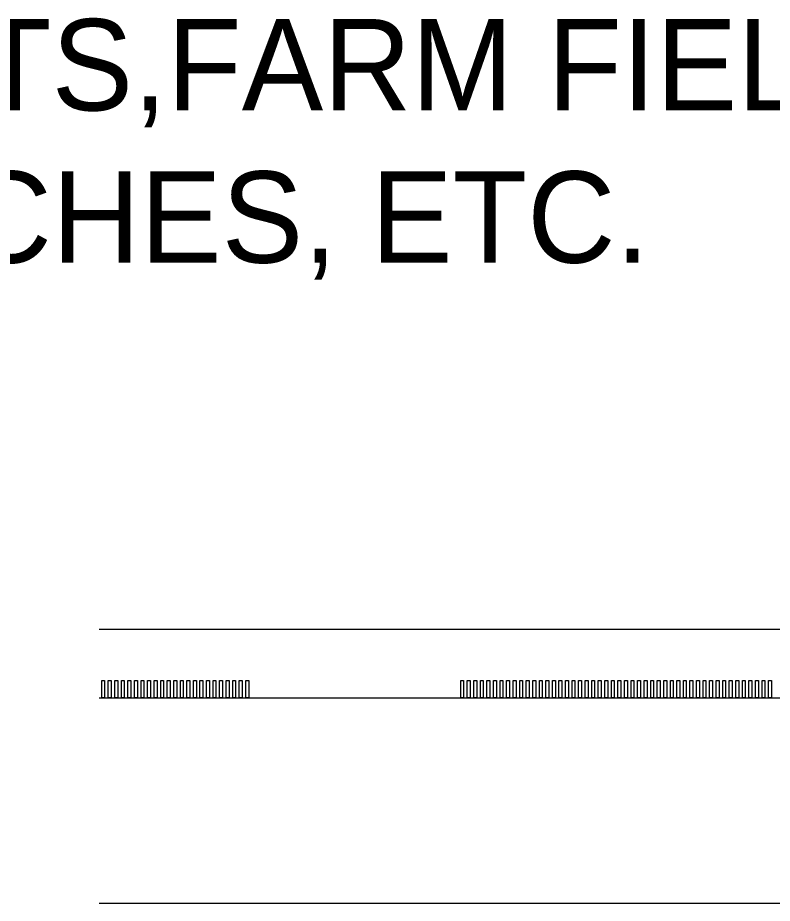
# Model space of a CAD drawing. Extents: x 49991.4 to 50021, y 49987.6 to 50011.4.
# Drawn here: x 50005.072 to 50005.567, y 49992.81 to 49993.391 of the extents above; entities that cross this region are included whole.
import ezdxf

# ---------------------------------------------------------------- set-up
doc = ezdxf.new("R2010")
doc.units = 0
doc.layers.add('Level 1', color=7, linetype='Continuous')
doc.layers.add('Level 2', color=7, linetype='Continuous')

msp = doc.modelspace()

# ---------------------------------------------------------------- linework, layer by layer
at = {"layer": 'Level 1'}
for p, q in [((50005.12506, 49992.9896), (50011.51026, 49992.9896)), ((50005.12506, 49992.9446), (50011.51026, 49992.9446)), ((50005.12506, 49992.8096), (50011.51026, 49992.8096))]:
    msp.add_line(p, q, dxfattribs=at)
for points in [[(50005.12859, 49992.9446), (50005.12669, 49992.9446), (50005.12669, 49992.9558), (50005.12859, 49992.9558)], [(50005.13289, 49992.9446), (50005.13099, 49992.9446), (50005.13099, 49992.9558), (50005.13289, 49992.9558)], [(50005.13719, 49992.9446), (50005.13529, 49992.9446), (50005.13529, 49992.9558), (50005.13719, 49992.9558)], [(50005.14149, 49992.9446), (50005.13959, 49992.9446), (50005.13959, 49992.9558), (50005.14149, 49992.9558)], [(50005.14579, 49992.9446), (50005.14389, 49992.9446), (50005.14389, 49992.9558), (50005.14579, 49992.9558)], [(50005.15009, 49992.9446), (50005.14819, 49992.9446), (50005.14819, 49992.9558), (50005.15009, 49992.9558)], [(50005.15439, 49992.9446), (50005.15249, 49992.9446), (50005.15249, 49992.9558), (50005.15439, 49992.9558)], [(50005.15869, 49992.9446), (50005.15679, 49992.9446), (50005.15679, 49992.9558), (50005.15869, 49992.9558)], [(50005.16299, 49992.9446), (50005.16109, 49992.9446), (50005.16109, 49992.9558), (50005.16299, 49992.9558)], [(50005.16729, 49992.9446), (50005.16539, 49992.9446), (50005.16539, 49992.9558), (50005.16729, 49992.9558)], [(50005.17159, 49992.9446), (50005.16969, 49992.9446), (50005.16969, 49992.9558), (50005.17159, 49992.9558)], [(50005.17589, 49992.9446), (50005.17399, 49992.9446), (50005.17399, 49992.9558), (50005.17589, 49992.9558)], [(50005.18019, 49992.9446), (50005.17829, 49992.9446), (50005.17829, 49992.9558), (50005.18019, 49992.9558)], [(50005.18449, 49992.9446), (50005.18259, 49992.9446), (50005.18259, 49992.9558), (50005.18449, 49992.9558)], [(50005.18879, 49992.9446), (50005.18689, 49992.9446), (50005.18689, 49992.9558), (50005.18879, 49992.9558)], [(50005.19309, 49992.9446), (50005.19119, 49992.9446), (50005.19119, 49992.9558), (50005.19309, 49992.9558)], [(50005.19739, 49992.9446), (50005.19549, 49992.9446), (50005.19549, 49992.9558), (50005.19739, 49992.9558)], [(50005.20169, 49992.9446), (50005.19979, 49992.9446), (50005.19979, 49992.9558), (50005.20169, 49992.9558)], [(50005.20599, 49992.9446), (50005.20409, 49992.9446), (50005.20409, 49992.9558), (50005.20599, 49992.9558)], [(50005.21029, 49992.9446), (50005.20839, 49992.9446), (50005.20839, 49992.9558), (50005.21029, 49992.9558)], [(50005.21459, 49992.9446), (50005.21269, 49992.9446), (50005.21269, 49992.9558), (50005.21459, 49992.9558)], [(50005.21889, 49992.9446), (50005.21699, 49992.9446), (50005.21699, 49992.9558), (50005.21889, 49992.9558)], [(50005.22319, 49992.9446), (50005.22129, 49992.9446), (50005.22129, 49992.9558), (50005.22319, 49992.9558)], [(50005.36429, 49992.9446), (50005.36239, 49992.9446), (50005.36239, 49992.9558), (50005.36429, 49992.9558)], [(50005.36859, 49992.9446), (50005.36669, 49992.9446), (50005.36669, 49992.9558), (50005.36859, 49992.9558)], [(50005.37289, 49992.9446), (50005.37099, 49992.9446), (50005.37099, 49992.9558), (50005.37289, 49992.9558)], [(50005.37719, 49992.9446), (50005.37529, 49992.9446), (50005.37529, 49992.9558), (50005.37719, 49992.9558)], [(50005.38149, 49992.9446), (50005.37959, 49992.9446), (50005.37959, 49992.9558), (50005.38149, 49992.9558)], [(50005.38579, 49992.9446), (50005.38389, 49992.9446), (50005.38389, 49992.9558), (50005.38579, 49992.9558)], [(50005.39009, 49992.9446), (50005.38819, 49992.9446), (50005.38819, 49992.9558), (50005.39009, 49992.9558)], [(50005.39439, 49992.9446), (50005.39249, 49992.9446), (50005.39249, 49992.9558), (50005.39439, 49992.9558)], [(50005.39869, 49992.9446), (50005.39679, 49992.9446), (50005.39679, 49992.9558), (50005.39869, 49992.9558)], [(50005.40299, 49992.9446), (50005.40109, 49992.9446), (50005.40109, 49992.9558), (50005.40299, 49992.9558)], [(50005.40729, 49992.9446), (50005.40539, 49992.9446), (50005.40539, 49992.9558), (50005.40729, 49992.9558)], [(50005.41159, 49992.9446), (50005.40969, 49992.9446), (50005.40969, 49992.9558), (50005.41159, 49992.9558)], [(50005.41589, 49992.9446), (50005.41399, 49992.9446), (50005.41399, 49992.9558), (50005.41589, 49992.9558)], [(50005.42019, 49992.9446), (50005.41829, 49992.9446), (50005.41829, 49992.9558), (50005.42019, 49992.9558)], [(50005.42449, 49992.9446), (50005.42259, 49992.9446), (50005.42259, 49992.9558), (50005.42449, 49992.9558)], [(50005.42879, 49992.9446), (50005.42689, 49992.9446), (50005.42689, 49992.9558), (50005.42879, 49992.9558)], [(50005.43309, 49992.9446), (50005.43119, 49992.9446), (50005.43119, 49992.9558), (50005.43309, 49992.9558)], [(50005.43739, 49992.9446), (50005.43549, 49992.9446), (50005.43549, 49992.9558), (50005.43739, 49992.9558)], [(50005.44169, 49992.9446), (50005.43979, 49992.9446), (50005.43979, 49992.9558), (50005.44169, 49992.9558)], [(50005.44599, 49992.9446), (50005.44409, 49992.9446), (50005.44409, 49992.9558), (50005.44599, 49992.9558)], [(50005.45029, 49992.9446), (50005.44839, 49992.9446), (50005.44839, 49992.9558), (50005.45029, 49992.9558)], [(50005.45459, 49992.9446), (50005.45269, 49992.9446), (50005.45269, 49992.9558), (50005.45459, 49992.9558)], [(50005.45889, 49992.9446), (50005.45699, 49992.9446), (50005.45699, 49992.9558), (50005.45889, 49992.9558)], [(50005.46319, 49992.9446), (50005.46129, 49992.9446), (50005.46129, 49992.9558), (50005.46319, 49992.9558)], [(50005.46749, 49992.9446), (50005.46559, 49992.9446), (50005.46559, 49992.9558), (50005.46749, 49992.9558)], [(50005.47179, 49992.9446), (50005.46989, 49992.9446), (50005.46989, 49992.9558), (50005.47179, 49992.9558)], [(50005.47609, 49992.9446), (50005.47419, 49992.9446), (50005.47419, 49992.9558), (50005.47609, 49992.9558)], [(50005.48039, 49992.9446), (50005.47849, 49992.9446), (50005.47849, 49992.9558), (50005.48039, 49992.9558)], [(50005.48469, 49992.9446), (50005.48279, 49992.9446), (50005.48279, 49992.9558), (50005.48469, 49992.9558)], [(50005.48899, 49992.9446), (50005.48709, 49992.9446), (50005.48709, 49992.9558), (50005.48899, 49992.9558)], [(50005.49329, 49992.9446), (50005.49139, 49992.9446), (50005.49139, 49992.9558), (50005.49329, 49992.9558)], [(50005.49759, 49992.9446), (50005.49569, 49992.9446), (50005.49569, 49992.9558), (50005.49759, 49992.9558)], [(50005.50189, 49992.9446), (50005.49999, 49992.9446), (50005.49999, 49992.9558), (50005.50189, 49992.9558)], [(50005.50619, 49992.9446), (50005.50429, 49992.9446), (50005.50429, 49992.9558), (50005.50619, 49992.9558)], [(50005.51049, 49992.9446), (50005.50859, 49992.9446), (50005.50859, 49992.9558), (50005.51049, 49992.9558)], [(50005.51479, 49992.9446), (50005.51289, 49992.9446), (50005.51289, 49992.9558), (50005.51479, 49992.9558)], [(50005.51909, 49992.9446), (50005.51719, 49992.9446), (50005.51719, 49992.9558), (50005.51909, 49992.9558)], [(50005.52339, 49992.9446), (50005.52149, 49992.9446), (50005.52149, 49992.9558), (50005.52339, 49992.9558)], [(50005.52769, 49992.9446), (50005.52579, 49992.9446), (50005.52579, 49992.9558), (50005.52769, 49992.9558)], [(50005.53199, 49992.9446), (50005.53009, 49992.9446), (50005.53009, 49992.9558), (50005.53199, 49992.9558)], [(50005.53629, 49992.9446), (50005.53439, 49992.9446), (50005.53439, 49992.9558), (50005.53629, 49992.9558)], [(50005.54059, 49992.9446), (50005.53869, 49992.9446), (50005.53869, 49992.9558), (50005.54059, 49992.9558)], [(50005.54489, 49992.9446), (50005.54299, 49992.9446), (50005.54299, 49992.9558), (50005.54489, 49992.9558)], [(50005.54919, 49992.9446), (50005.54729, 49992.9446), (50005.54729, 49992.9558), (50005.54919, 49992.9558)], [(50005.55349, 49992.9446), (50005.55159, 49992.9446), (50005.55159, 49992.9558), (50005.55349, 49992.9558)], [(50005.55779, 49992.9446), (50005.55589, 49992.9446), (50005.55589, 49992.9558), (50005.55779, 49992.9558)], [(50005.56209, 49992.9446), (50005.56019, 49992.9446), (50005.56019, 49992.9558), (50005.56209, 49992.9558)], [(50005.56639, 49992.9446), (50005.56449, 49992.9446), (50005.56449, 49992.9558), (50005.56639, 49992.9558)]]:
    msp.add_lwpolyline(points, close=True, dxfattribs=at)

# ---------------------------------------------------------------- texts
at = {"layer": 'Level 2'}
for s, p in [('MARKER TURNOUTS,FARM FIELD APPROACHES,', (50004.336, 49993.3302)), ('PRIVATE APPROACHES, ETC.', (50004.336, 49993.2302))]:
    msp.add_text(s, height=0.06, dxfattribs=at).set_placement(p)

doc.saveas('drawing.dxf')
